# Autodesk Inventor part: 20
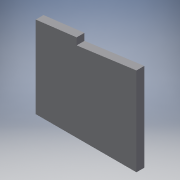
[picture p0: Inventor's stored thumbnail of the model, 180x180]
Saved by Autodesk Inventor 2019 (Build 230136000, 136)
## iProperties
Created: 2019-01
Part Number: 20
Material: Generic
Document SubType Name: Modeling
Designer: Guy Link
Density: 1 g/cm^3
Appearance: Default
Author: Guy Link
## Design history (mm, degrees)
sketch "Sketch1"
  geometry: L1 (0, 0)-(40.64, 0); L2 (40.64, 0)-(40.64, 33.02); L3 (0, 33.02)-(0, 0); L4 (40.64, 0)-(40.64, 35.56); L5 (16.51, 32.258)-(40.64, 35.56); L6 (16.51, 32.258)-(16.51, 35.052); L7 (16.51, 35.052)-(0, 33.02)
  constraints: 14 end point, 1 horizontal, 1 parallel, 1 perpendicular, 1 point on line
  dimensions: "d0" = 40.64 distance of L3.start L2.end; "d1" = 33.02 distance of L2.end L1.end; "d2" = 35.56 distance of L1.end L4.end; "d5" = 2.794 distance of L5.start L6.end
extrude "Extrusion1" new body sketch "Sketch1" distance "d6" = 3.175; taper "d7" = 0 deg
body "Solid1"
